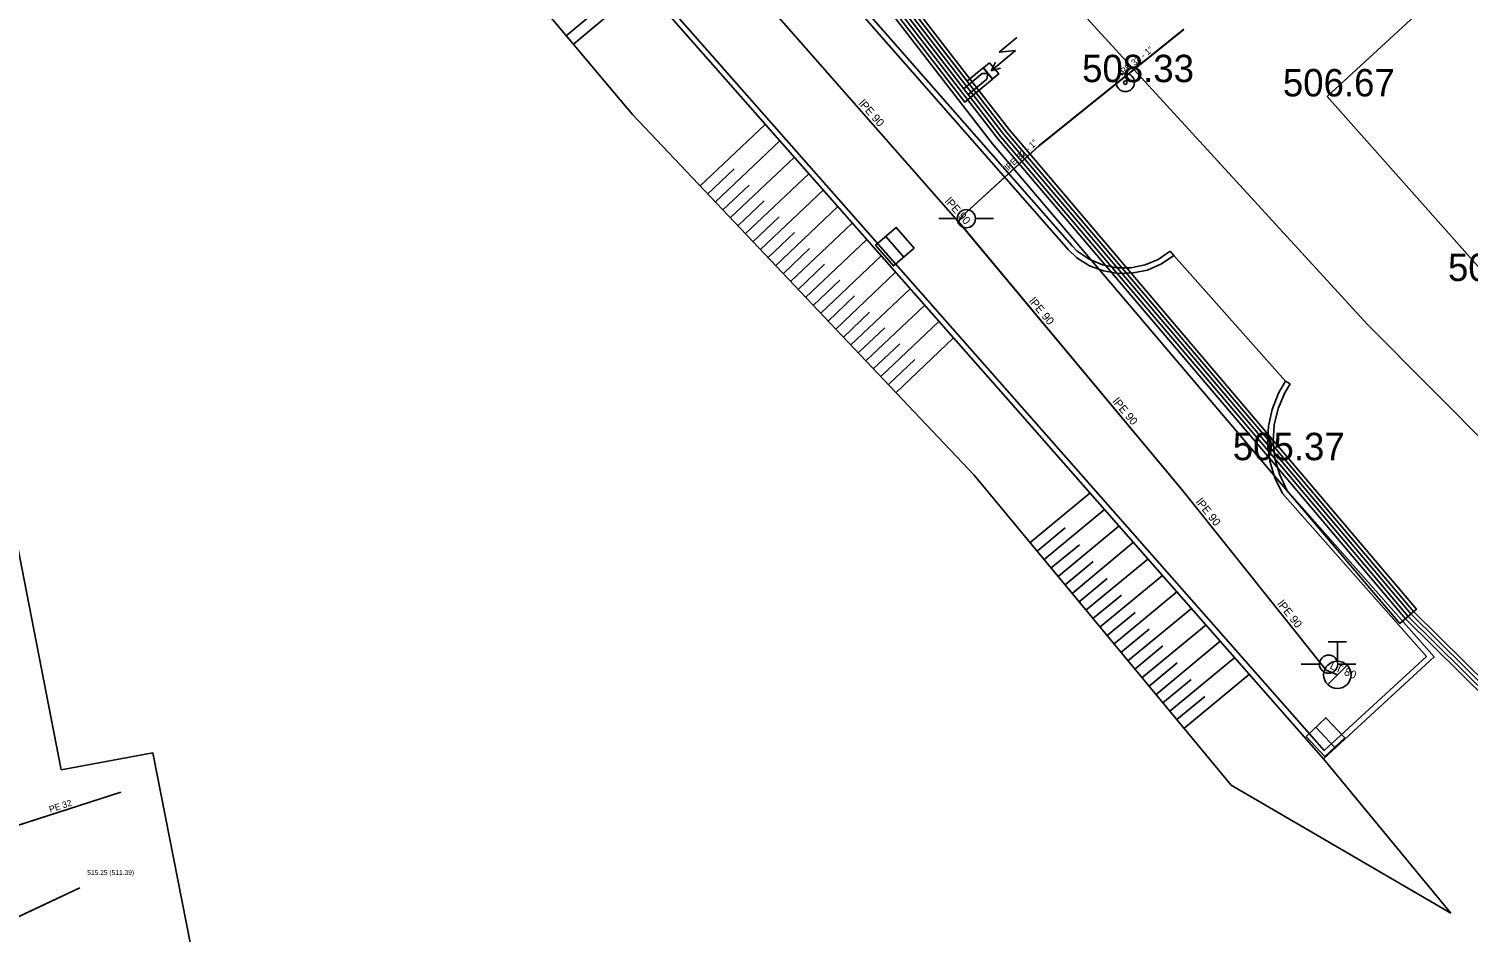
# Model space of a CAD drawing. Extents: x -668867 to -667827, y -1131943 to -1131019.
# Drawn here: x -668363.35 to -668323.89, y -1131427.79 to -1131403.03 of the extents above; entities that cross this region are included whole.
import ezdxf

# ---------------------------------------------------------------- set-up
doc = ezdxf.new("R2010")
doc.units = 0
for name, color, linetype in [('G_Bod_tecka', 7, 'Continuous'), ('G_Bod_vyska', 7, 'Continuous'), ('G_Breh_Teren', 7, 'Continuous'), ('G_Budovy_Objekty', 7, 'Continuous'), ('G_Cesty_Schody', 7, 'Continuous'), ('G_Plochy_zpevnene', 7, 'Continuous'), ('G_Site-kanalizace', 7, 'Continuous'), ('G_Site-Rozvadece', 7, 'Continuous'), ('G_Site-Sloupy', 7, 'Continuous'), ('G_Site-vodovod', 7, 'Continuous'), ('G_Vyskove_srafy', 7, 'Continuous'), ('G_Z_CHRANICKA-TEPLOVOD_kotovane', 7, 'Continuous'), ('G_Z_ELsilove_podz_kotovane', 7, 'Continuous'), ('G_Z_ELsilove_zrusene', 7, 'Continuous'), ('G_Z_KANAL_podz_kotovane', 7, 'Continuous'), ('G_Z_SPOJE_podz_kotovane', 7, 'Continuous'), ('G_Z_VODA_podz_kotovane', 7, 'Continuous'), ('Vrstva 18', 7, 'Continuous'), ('Vrstva 2', 7, 'Continuous'), ('Vrstva 26', 7, 'Continuous'), ('Vrstva 4', 7, 'Continuous'), ('Vrstva 6', 7, 'Continuous'), ('Vrstva 7', 7, 'Continuous'), ('Vrstva 8', 7, 'Continuous')]:
    doc.layers.add(name, color=color, linetype=linetype)

msp = doc.modelspace()

# ---------------------------------------------------------------- linework, layer by layer
at = {"layer": 'G_Bod_tecka'}
for p, q in [((-668333.29, -1131404.49), (-668333.29, -1131404.49)), ((-668327.76, -1131404.88), (-668327.76, -1131404.88)), ((-668329.16, -1131414.85), (-668329.16, -1131414.85))]:
    msp.add_line(p, q, dxfattribs=at)
at = {"layer": 'G_Breh_Teren'}
for p, q in [((-668346.8, -1131405.38), (-668353.24, -1131397.71)), ((-668337.43, -1131415.26), (-668346.8, -1131405.38)), ((-668330.39, -1131423.76), (-668337.43, -1131415.26)), ((-668327.86, -1131423.03), (-668324.37, -1131427.26)), ((-668324.37, -1131427.26), (-668330.39, -1131423.76))]:
    msp.add_line(p, q, dxfattribs=at)
at = {"layer": 'G_Budovy_Objekty'}
for p, q in [((-668327.76, -1131404.88), (-668321.76, -1131399.36)), ((-668323.26, -1131409.94), (-668327.76, -1131404.88)), ((-668362.46, -1131423.34), (-668364.22, -1131414.33)), ((-668359.95, -1131422.87), (-668362.46, -1131423.34)), ((-668356.4, -1131440.88), (-668359.95, -1131422.87))]:
    msp.add_line(p, q, dxfattribs=at)
at = {"layer": 'G_Cesty_Schody'}
for points in [[(-668355.38, -1131391.54), (-668348.83, -1131398.98), (-668336.33, -1131413.17), (-668327.84, -1131422.81), (-668325.04, -1131420.23), (-668328.98, -1131415.76)], [(-668334.86, -1131409.08), (-668342.28, -1131400.62)], [(-668331.96, -1131409.24), (-668332.3, -1131409.47), (-668332.68, -1131409.64), (-668333.08, -1131409.72), (-668333.49, -1131409.73), (-668333.89, -1131409.66), (-668334.27, -1131409.52), (-668334.62, -1131409.3), (-668334.86, -1131409.08)], [(-668328.98, -1131415.76), (-668329.19, -1131415.33), (-668329.33, -1131414.88), (-668329.39, -1131414.4), (-668329.37, -1131413.92), (-668329.27, -1131413.46), (-668329.09, -1131413.01), (-668328.9, -1131412.68)]]:
    msp.add_lwpolyline(points, dxfattribs=at)
at = {"layer": 'G_Plochy_zpevnene'}
for p, q in [((-668331.96, -1131409.24), (-668332.06, -1131409.12)), ((-668328.9, -1131412.68), (-668331.96, -1131409.24)), ((-668328.77, -1131412.76), (-668328.9, -1131412.68))]:
    msp.add_line(p, q, dxfattribs=at)
for points in [[(-668355.49, -1131391.64), (-668348.94, -1131399.08), (-668336.44, -1131413.27), (-668327.86, -1131423.03), (-668324.83, -1131420.24), (-668328.86, -1131415.67)], [(-668334.75, -1131408.98), (-668342.16, -1131400.53)], [(-668332.06, -1131409.12), (-668332.39, -1131409.35), (-668332.75, -1131409.5), (-668333.14, -1131409.58), (-668333.53, -1131409.58), (-668333.92, -1131409.5), (-668334.28, -1131409.34), (-668334.61, -1131409.12), (-668334.75, -1131408.98)], [(-668328.86, -1131415.67), (-668329.06, -1131415.25), (-668329.19, -1131414.81), (-668329.24, -1131414.34), (-668329.21, -1131413.88), (-668329.1, -1131413.43), (-668328.92, -1131413), (-668328.77, -1131412.76)]]:
    msp.add_lwpolyline(points, dxfattribs=at)
at = {"layer": 'G_Site-kanalizace'}
for p, q in [((-668339.855, -1131408.716), (-668339.365, -1131409.284)), ((-668328.066, -1131422.166), (-668327.554, -1131422.714))]:
    msp.add_line(p, q, dxfattribs=at)
for points in [[(-668340.138, -1131408.961), (-668339.647, -1131409.528), (-668339.08, -1131409.038), (-668339.571, -1131408.47)], [(-668328.339, -1131422.421), (-668327.827, -1131422.969), (-668327.279, -1131422.457), (-668327.791, -1131421.909)]]:
    msp.add_lwpolyline(points, close=True, dxfattribs=at)
at = {"layer": 'G_Site-Rozvadece'}
for p, q in [((-668336.266, -1131403.267), (-668336.746, -1131403.667)), ((-668336.298, -1131403.619), (-668336.97, -1131404.18)), ((-668336.746, -1131403.667), (-668336.298, -1131403.619)), ((-668336.853, -1131403.938), (-668336.97, -1131404.18)), ((-668336.97, -1131404.18), (-668336.712, -1131404.107))]:
    msp.add_line(p, q, dxfattribs=at)
msp.add_lwpolyline([(-668337.01, -1131403.96), (-668337.18, -1131404.1), (-668336.93, -1131404.4), (-668336.76, -1131404.26)], close=True, dxfattribs=at)
at = {"layer": 'G_Site-Sloupy'}
for radius in [0.25, 0.05]:
    msp.add_circle((-668333.29, -1131404.5), radius, dxfattribs=at)
at = {"layer": 'G_Site-vodovod'}
for p, q in [((-668337.9, -1131408.23), (-668338.4, -1131408.23)), ((-668337.4, -1131408.23), (-668336.9, -1131408.23)), ((-668327.73, -1131419.83), (-668327.23, -1131419.83)), ((-668327.48, -1131420.355), (-668327.48, -1131419.83)), ((-668327.97, -1131420.44), (-668328.47, -1131420.44)), ((-668327.745, -1131420.995), (-668327.215, -1131420.465)), ((-668327.47, -1131420.44), (-668326.97, -1131420.44))]:
    msp.add_line(p, q, dxfattribs=at)
for centre, radius in [((-668337.65, -1131408.23), 0.25), ((-668327.72, -1131420.44), 0.25), ((-668327.48, -1131420.73), 0.375)]:
    msp.add_circle(centre, radius, dxfattribs=at)
at = {"layer": 'G_Vyskove_srafy'}
for p, q in [((-668348.42, -1131403.45), (-668346.51, -1131401.85)), ((-668348.62, -1131403.22), (-668347.85, -1131402.58)), ((-668344.95, -1131407.34), (-668343.16, -1131405.65)), ((-668344.53, -1131407.78), (-668342.76, -1131406.1)), ((-668344.74, -1131407.56), (-668344.01, -1131406.87)), ((-668344.12, -1131408.21), (-668342.36, -1131406.55)), ((-668344.33, -1131408), (-668343.6, -1131407.31)), ((-668343.71, -1131408.65), (-668341.97, -1131407)), ((-668343.29, -1131409.08), (-668341.57, -1131407.45)), ((-668343.91, -1131408.43), (-668343.19, -1131407.74)), ((-668342.88, -1131409.52), (-668341.17, -1131407.9)), ((-668343.5, -1131408.87), (-668342.78, -1131408.18)), ((-668342.47, -1131409.95), (-668340.78, -1131408.35)), ((-668343.09, -1131409.3), (-668342.36, -1131408.61)), ((-668342.06, -1131410.39), (-668340.38, -1131408.8)), ((-668342.67, -1131409.74), (-668341.95, -1131409.05)), ((-668341.64, -1131410.82), (-668339.98, -1131409.25)), ((-668342.26, -1131410.17), (-668341.54, -1131409.48)), ((-668341.85, -1131410.61), (-668341.12, -1131409.92)), ((-668341.23, -1131411.26), (-668339.59, -1131409.7)), ((-668341.44, -1131411.04), (-668340.71, -1131410.35)), ((-668340.82, -1131411.7), (-668339.19, -1131410.15)), ((-668341.02, -1131411.48), (-668340.3, -1131410.79)), ((-668340.4, -1131412.13), (-668338.79, -1131410.6)), ((-668340.61, -1131411.91), (-668339.88, -1131411.22)), ((-668339.99, -1131412.56), (-668338.4, -1131411.05)), ((-668339.58, -1131413), (-668338, -1131411.5)), ((-668340.2, -1131412.35), (-668339.47, -1131411.66)), ((-668339.78, -1131412.78), (-668339.06, -1131412.09)), ((-668335.9, -1131417.11), (-668334.26, -1131415.75)), ((-668335.52, -1131417.57), (-668333.86, -1131416.2)), ((-668335.71, -1131417.34), (-668334.94, -1131416.7)), ((-668335.13, -1131418.04), (-668333.46, -1131416.65)), ((-668335.32, -1131417.8), (-668334.55, -1131417.17)), ((-668334.75, -1131418.5), (-668333.07, -1131417.1)), ((-668334.37, -1131418.96), (-668332.67, -1131417.56)), ((-668334.94, -1131418.27), (-668334.17, -1131417.63)), ((-668334.56, -1131418.73), (-668333.79, -1131418.09)), ((-668333.98, -1131419.42), (-668332.27, -1131418.01)), ((-668334.18, -1131419.19), (-668333.4, -1131418.55)), ((-668333.6, -1131419.88), (-668331.88, -1131418.46)), ((-668333.79, -1131419.65), (-668333.02, -1131419.02)), ((-668333.22, -1131420.35), (-668331.48, -1131418.91)), ((-668333.41, -1131420.12), (-668332.64, -1131419.48)), ((-668332.84, -1131420.81), (-668331.08, -1131419.36)), ((-668333.03, -1131420.58), (-668332.26, -1131419.94)), ((-668332.45, -1131421.27), (-668330.69, -1131419.81)), ((-668332.07, -1131421.73), (-668330.29, -1131420.26)), ((-668332.64, -1131421.04), (-668331.87, -1131420.4)), ((-668331.69, -1131422.2), (-668329.89, -1131420.71)), ((-668332.26, -1131421.5), (-668331.49, -1131420.86)), ((-668331.88, -1131421.96), (-668331.11, -1131421.33))]:
    msp.add_line(p, q, dxfattribs=at)
at = {"layer": 'G_Z_CHRANICKA-TEPLOVOD_kotovane'}
msp.add_lwpolyline([(-668366.49, -1131364.819), (-668361.978, -1131371.193), (-668355.865, -1131379.487), (-668350.614, -1131387.7), (-668350.613, -1131387.701), (-668349.219, -1131389.792), (-668342.973, -1131397.546), (-668337.629, -1131404.464), (-668337.551, -1131404.399), (-668337.188, -1131404.096), (-668336.932, -1131404.404), (-668337.307, -1131404.716), (-668337.691, -1131405.036), (-668343.287, -1131397.794), (-668349.541, -1131390.028), (-668350.946, -1131387.92), (-668350.947, -1131387.919), (-668356.195, -1131379.713), (-668362.302, -1131371.427), (-668366.81, -1131365.061)], dxfattribs=at)
msp.add_lwpolyline([(-668350.614, -1131387.7), (-668350.53, -1131387.644), (-668349.138, -1131389.732), (-668342.894, -1131397.484), (-668337.551, -1131404.399), (-668337.307, -1131404.716), (-668336.476, -1131405.791), (-668325.311, -1131418.936), (-668325.768, -1131419.324), (-668336.933, -1131406.179), (-668343.366, -1131397.856), (-668349.622, -1131390.088), (-668351.03, -1131387.976), (-668350.946, -1131387.92)], close=True, dxfattribs=at)
at = {"layer": 'G_Z_ELsilove_podz_kotovane'}
for points in [[(-668408.95, -1131333.1), (-668406.83, -1131330.34), (-668406.29, -1131329.53), (-668406.257, -1131329.495), (-668405.49, -1131328.67), (-668399.24, -1131323.79), (-668397.09, -1131324.16), (-668396.08, -1131324.9), (-668391.49, -1131330.34), (-668386.5, -1131336.42), (-668385.67, -1131337.67), (-668385.49, -1131339.6), (-668385.39, -1131341.8), (-668384.66, -1131342.96), (-668373.89, -1131355.96), (-668366.65, -1131364.94), (-668362.14, -1131371.31), (-668356.03, -1131379.6), (-668350.78, -1131387.81), (-668349.38, -1131389.91), (-668343.13, -1131397.67), (-668337.721, -1131404.671), (-668337.216, -1131404.25), (-668337.06, -1131404.25)], [(-668366.73, -1131365), (-668362.221, -1131371.369), (-668356.112, -1131379.657), (-668350.864, -1131387.865), (-668349.461, -1131389.969), (-668343.209, -1131397.732), (-668336.778, -1131406.053), (-668329.236, -1131414.915), (-668325.613, -1131419.198), (-668318.049, -1131426.672), (-668308.959, -1131435.142)], [(-668366.57, -1131364.88), (-668362.059, -1131371.251), (-668355.948, -1131379.543), (-668350.696, -1131387.755), (-668349.299, -1131389.851), (-668343.051, -1131397.608), (-668336.622, -1131405.927), (-668329.084, -1131414.785), (-668325.467, -1131419.062), (-668317.911, -1131426.528), (-668308.821, -1131434.998)], [(-668337.06, -1131404.25), (-668337.088, -1131404.404), (-668337.599, -1131404.829), (-668336.7, -1131405.99), (-668329.16, -1131414.85), (-668325.54, -1131419.13), (-668317.98, -1131426.6), (-668308.89, -1131435.07), (-668300.42, -1131443.36), (-668291.43, -1131452.44), (-668287.59, -1131456.65), (-668283.35, -1131461.3), (-668283.359, -1131462.295), (-668283.803, -1131462.975), (-668286.795, -1131467.437), (-668290.099, -1131473.205), (-668291.985, -1131477.429), (-668292.115, -1131478.379), (-668292.631, -1131479.029)]]:
    msp.add_lwpolyline(points, dxfattribs=at)
at = {"layer": 'G_Z_ELsilove_zrusene'}
msp.add_lwpolyline([(-668307.243, -1131431.203), (-668317.995, -1131419.84), (-668326.659, -1131411.121), (-668334.853, -1131402.182), (-668341.39, -1131394.475), (-668345.534, -1131389.961), (-668348.109, -1131387.508), (-668349.338, -1131386.039), (-668349.614, -1131385.544), (-668349.891, -1131385.05), (-668350.277, -1131382.705), (-668349.451, -1131378.507), (-668349.526, -1131377.414), (-668350.334, -1131375.359), (-668361.51, -1131362.724), (-668372.64, -1131350.72)], dxfattribs=at)
msp.add_lwpolyline([(-668307.243, -1131431.203), (-668317.995, -1131419.84), (-668326.659, -1131411.121), (-668334.853, -1131402.182), (-668341.39, -1131394.475), (-668345.534, -1131389.961), (-668348.109, -1131387.508), (-668349.338, -1131386.039), (-668349.614, -1131385.544), (-668349.891, -1131385.05), (-668350.277, -1131382.705), (-668349.451, -1131378.507), (-668349.526, -1131377.414), (-668350.334, -1131375.359), (-668361.51, -1131362.724), (-668372.64, -1131350.72)], dxfattribs=at)
at = {"layer": 'G_Z_KANAL_podz_kotovane'}
msp.add_line((-668361.95, -1131426.57), (-668370.23, -1131430.47), dxfattribs=at)
at = {"layer": 'G_Z_SPOJE_podz_kotovane'}
for points in [[(-668366.65, -1131364.94), (-668362.14, -1131371.31), (-668356.03, -1131379.6), (-668350.78, -1131387.81), (-668349.38, -1131389.91), (-668343.13, -1131397.67), (-668336.7, -1131405.99), (-668329.16, -1131414.85), (-668325.54, -1131419.13), (-668317.98, -1131426.6), (-668308.89, -1131435.07)], [(-668366.65, -1131364.94), (-668362.14, -1131371.31), (-668356.03, -1131379.6), (-668350.78, -1131387.81), (-668349.38, -1131389.91), (-668343.13, -1131397.67), (-668336.7, -1131405.99), (-668329.16, -1131414.85), (-668325.54, -1131419.13), (-668317.98, -1131426.6), (-668308.89, -1131435.07)], [(-668366.491, -1131364.82), (-668361.978, -1131371.193), (-668355.865, -1131379.486), (-668350.612, -1131387.7), (-668349.218, -1131389.791), (-668342.973, -1131397.546), (-668336.544, -1131405.864), (-668329.008, -1131414.72), (-668325.393, -1131418.994), (-668317.841, -1131426.455), (-668308.752, -1131434.926)]]:
    msp.add_lwpolyline(points, dxfattribs=at)
at = {"layer": 'G_Z_VODA_podz_kotovane'}
msp.add_line((-668327.79, -1131420.6), (-668327.48, -1131420.73), dxfattribs=at)
for points in [[(-668371.54, -1131366.16), (-668371.4, -1131366.07), (-668370.38, -1131365.25), (-668367.57, -1131368.89), (-668364.45, -1131374.04), (-668361.42, -1131379.18), (-668358.58, -1131384.1), (-668354.88, -1131388.99), (-668350.92, -1131393.63), (-668343.05, -1131402.42), (-668337.87, -1131408.31), (-668331.71, -1131415.7), (-668327.79, -1131420.6)], [(-668337.87, -1131408.31), (-668337.76, -1131408.16), (-668335.65, -1131406.23), (-668331.69, -1131403.04)], [(-668368.16, -1131426.31), (-668368.06, -1131426.28), (-668360.82, -1131423.95)]]:
    msp.add_lwpolyline(points, dxfattribs=at)
at = {"layer": 'Vrstva 18'}
msp.add_line((-668361.95, -1131426.57), (-668370.232, -1131430.47), dxfattribs=at)
at = {"layer": 'Vrstva 26'}
msp.add_line((-668327.786, -1131420.6), (-668327.477, -1131420.733), dxfattribs=at)
for points in [[(-668371.539, -1131366.156), (-668371.405, -1131366.074), (-668370.38, -1131365.247), (-668367.57, -1131368.894), (-668364.452, -1131374.041), (-668361.418, -1131379.182), (-668358.584, -1131384.105), (-668354.881, -1131388.995), (-668350.925, -1131393.632), (-668343.054, -1131402.423), (-668337.866, -1131408.307), (-668331.706, -1131415.695), (-668327.786, -1131420.6)], [(-668337.866, -1131408.307), (-668337.762, -1131408.159), (-668335.651, -1131406.231), (-668331.689, -1131403.045)], [(-668368.163, -1131426.312), (-668368.055, -1131426.277), (-668360.82, -1131423.95)]]:
    msp.add_lwpolyline(points, dxfattribs=at)
at = {"layer": 'Vrstva 6'}
for p, q in [((-668337.762, -1131408.159), (-668337.762, -1131408.159)), ((-668327.786, -1131420.6), (-668327.786, -1131420.6))]:
    msp.add_line(p, q, dxfattribs=at)
at = {"layer": 'Vrstva 7'}
msp.add_line((-668327.477, -1131420.733), (-668327.477, -1131420.733), dxfattribs=at)
at = {"layer": 'Vrstva 8'}
msp.add_line((-668361.95, -1131426.57), (-668361.95, -1131426.57), dxfattribs=at)

# ---------------------------------------------------------------- texts
at = {"layer": 'G_Bod_vyska'}
for s, p in [('508.33', (-668334.476, -1131404.49)), ('506.67', (-668328.973, -1131404.88)), ('505.59', (-668324.448, -1131409.94)), ('505.37', (-668330.346, -1131414.85))]:
    msp.add_text(s, height=0.75, dxfattribs=at).set_placement(p)
at = {"layer": 'Vrstva 2'}
msp.add_text('515.25 (511.39)', height=0.13163, dxfattribs=at).set_placement((-668361.744, -1131426.217))
at = {"layer": 'Vrstva 4'}
for s, height, rotation, p in [('lPE 32 - 1"', 0.17551, 38.7731, (-668333.378, -1131404.324)), ('lPE 90', 0.2194, 311.3929, (-668340.614, -1131405.083)), ('lPE 32 - 1"', 0.17551, 42.3948, (-668336.503, -1131406.925)), ('lPE 90', 0.2194, 311.3929, (-668338.25, -1131407.766)), ('lPE 90', 0.2194, 309.822, (-668335.945, -1131410.501)), ('lPE 90', 0.2194, 309.869, (-668333.654, -1131413.248)), ('lPE 90', 0.2194, 308.6312, (-668331.371, -1131416.001)), ('lPE 90', 0.2194, 308.6312, (-668329.138, -1131418.794)), ('LT 80', 0.2194, 336.6916, (-668327.704, -1131420.558)), ('PE 32', 0.1755, 17.858, (-668362.758, -1131424.509))]:
    msp.add_text(s, height=height, rotation=rotation, dxfattribs=at).set_placement(p)

doc.saveas('drawing.dxf')
